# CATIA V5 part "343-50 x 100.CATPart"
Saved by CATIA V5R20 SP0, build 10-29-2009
Part number: 343-50 x 100
Definition: NONE
Nomenclature: 343-50 x 100
Source: Unknown
Description: 343-50 x 100
Bounding box of the stored display mesh (mm): x 0 to 100, y -35 to 35, z -35 to 35
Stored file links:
  C:\Users\Utente\Desktop\IO LAVORO\3D X SITO CF\X SITO\343-348\343-50 x 100.CATPart
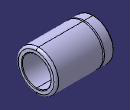
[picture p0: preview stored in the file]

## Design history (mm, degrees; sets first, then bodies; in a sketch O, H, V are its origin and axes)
Body1 "343-50 x 100" (main body)
  Solid1: solid without history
